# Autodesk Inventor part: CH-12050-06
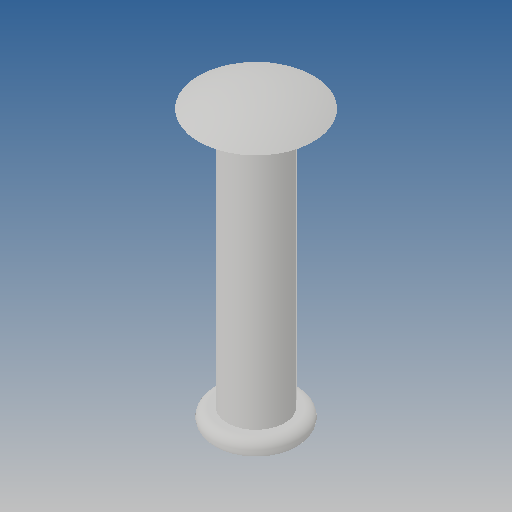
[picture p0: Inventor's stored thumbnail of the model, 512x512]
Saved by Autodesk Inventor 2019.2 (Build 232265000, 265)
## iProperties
Created: 2012-07
Part Number: CH-12050-06
Material: Ogólny
Document SubType Name: Modeling
Designer: CADENGINEERING4
Density: 1 g/cm^3
Appearance: Domyślna
Author: CADENGINEERING4
Revision Number: ÈÎºÎ
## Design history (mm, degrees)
feature "Ô²½Ç2"
node "Bryła1"
